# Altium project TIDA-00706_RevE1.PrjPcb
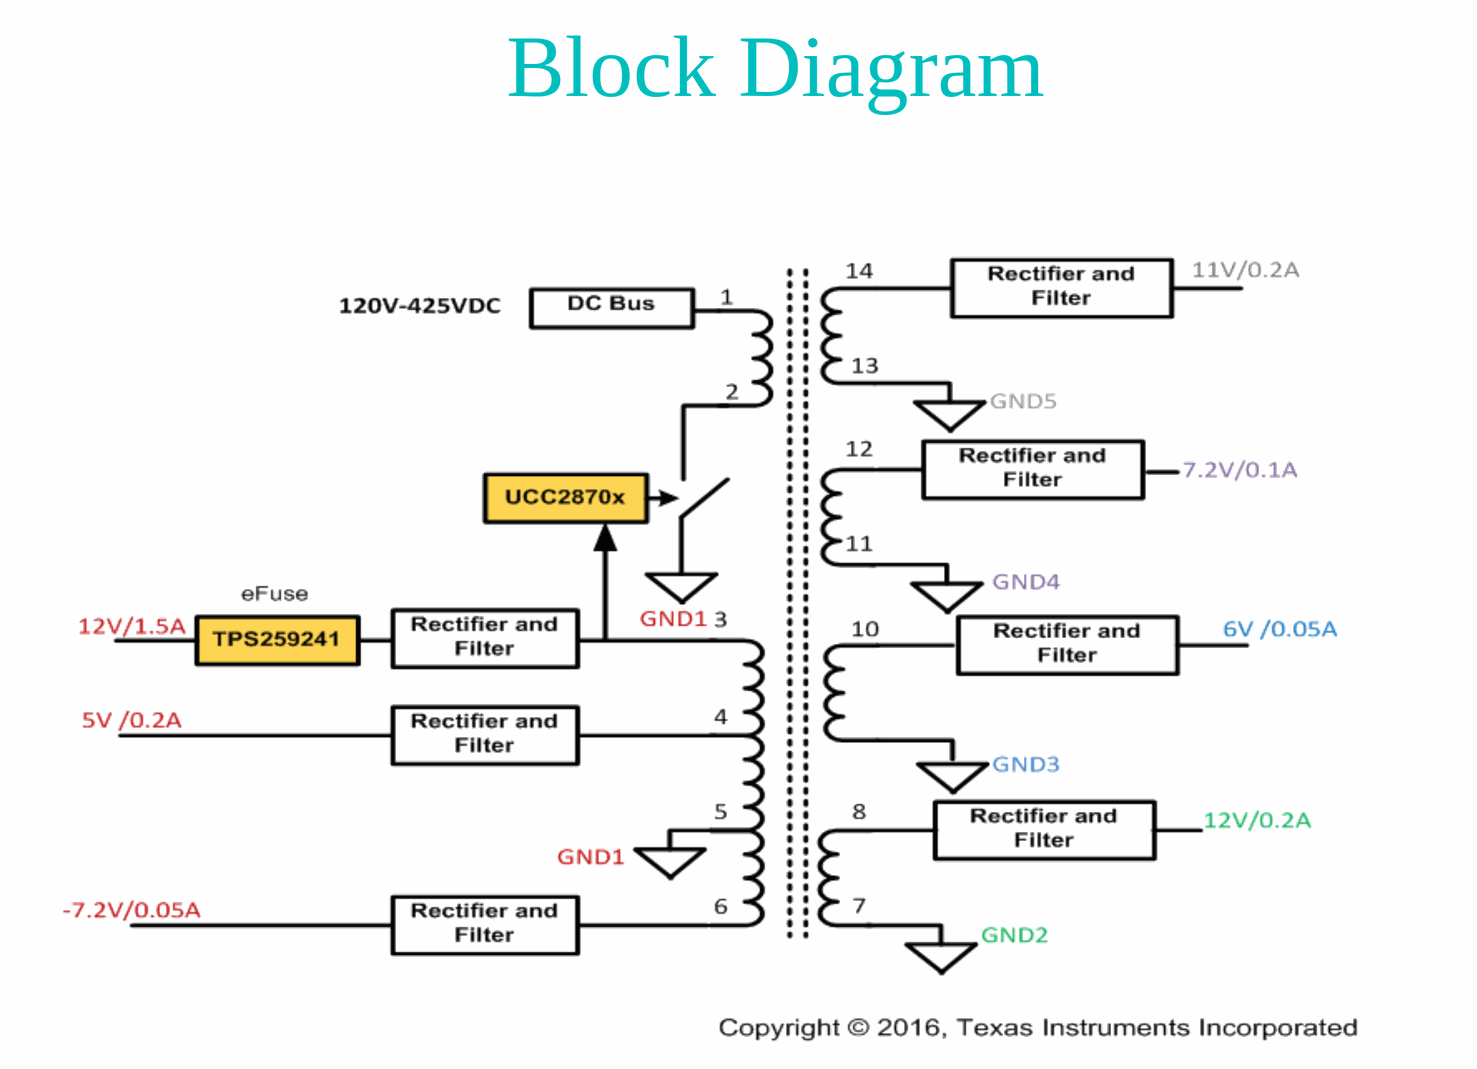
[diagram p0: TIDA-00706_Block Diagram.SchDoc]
CopyrightYear: 2016; EVM_Orderable: N/A; PCB_Layout: Manjunatha T N; PCB_Rev: E1; PRJ_Customer: Public Release; PRJ_Engineer: Neha Nain; PRJ_Number: TIDA-00706; PRJ_Title: 25W High Eff. Multipule output Auxilary Supply for Server PSU; SCH_Rev: E1; TechSupport: http://www.ti.com/support; TID: TIDA-00706
3 sheets, 66 parts. Net scope: flat (ports and power ports of the same name join across sheets).
Board file: TIDA-00706_RevE1.PcbDoc
Sheets:
  TIDA-00706_Block Diagram.SchDoc
  TIDA-00706_Schematics.SchDoc
  TIDA-00706_Hardware.SchDoc

## Sheet TIDA-00706_Block Diagram.SchDoc
size 431 x 304 mm; Date: Not shown in title block; ApprovedBy: Not shown in title block; CheckedBy: Not shown in title block; Author: Ramkumar S; CompanyName: Not shown in title block; DrawnBy: Naina Neha; Engineer: Naina Neha; Organization: Not shown in title block; Address1: Not shown in title block; Address2: Not shown in title block; Address3: Not shown in title block; Address4: Not shown in title block; DocumentNumber: 1; Revision: Use project parameter SCH_Rev; SheetNumber: 1; SheetTotal: 3; PageSetup: Record=PageOptions¦CenterHorizontal=True¦CenterVertical=True¦PrintScale=1.00¦XCorrection=1.00¦YCorrection=1.00¦PrintKind=0¦BorderSize=5000000¦LeftOffset=0¦BottomOffset=0¦Orientation=2¦PaperLength=1000¦PaperWidth=1000¦Scale=100¦PaperSource=15¦PrintQuality=600¦MediaType=1¦DitherType=10¦PaperKind=Letter¦PrintScaleMode=1

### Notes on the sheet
- Block Diagram

## Sheet TIDA-00706_Schematics.SchDoc
size 431 x 279 mm; Date: Not shown in title block; ApprovedBy: Not shown in title block; CheckedBy: Not shown in title block; Author: Not shown in title block; CompanyName: Not shown in title block; DrawnBy: Neha Nain; Engineer: Not shown in title block; Organization: Not shown in title block; Address1: Not shown in title block; Address2: Not shown in title block; Address3: Not shown in title block; Address4: Not shown in title block; DocumentNumber: 1; Revision: Use project parameter SCH_Rev; SheetNumber: 2; SheetTotal: 3; PageSetup: Record=PageOptions¦CenterHorizontal=True¦CenterVertical=True¦PrintScale=1.00¦XCorrection=1.00¦YCorrection=1.00¦PrintKind=0¦BorderSize=5000000¦LeftOffset=0¦BottomOffset=0¦Orientation=2¦PaperLength=1000¦PaperWidth=1000¦Scale=100¦PaperSource=15¦PrintQuality=600¦MediaType=1¦DitherType=10¦PaperKind=Letter¦PrintScaleMode=1
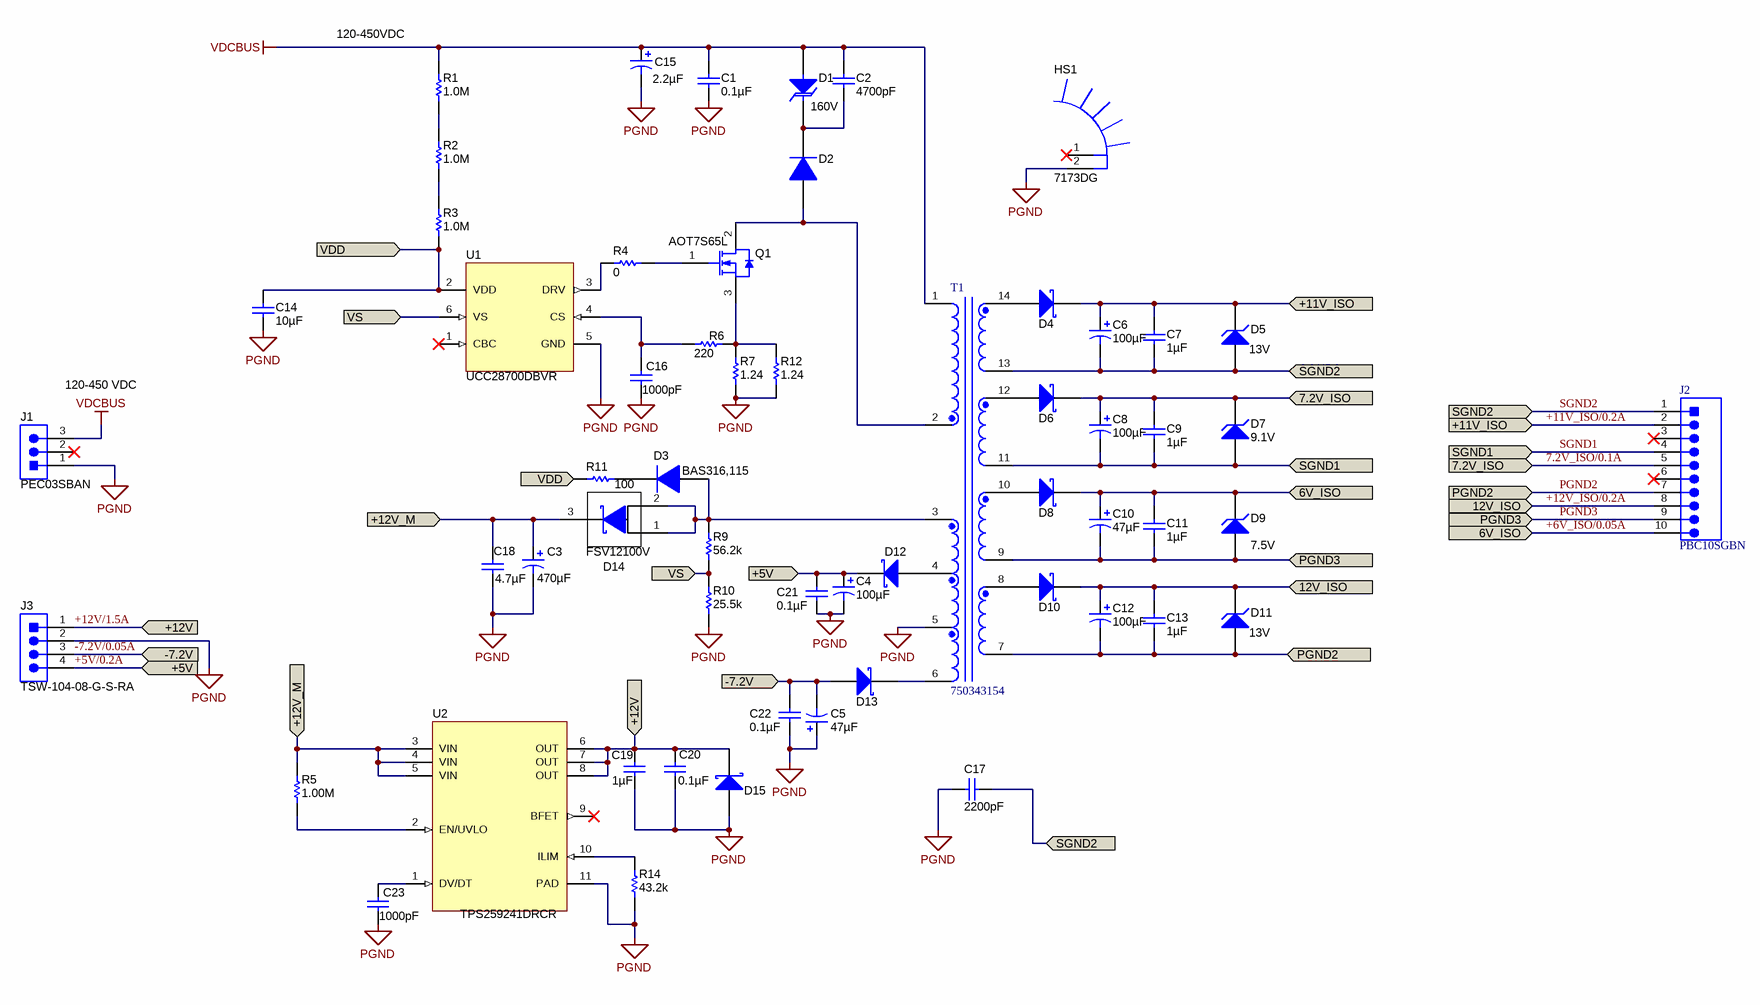
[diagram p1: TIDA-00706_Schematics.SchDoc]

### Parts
C1  ValueDisplayed: 0.1µF  [WCAP-FTXX_P10PL20_13x5x11]  (hidden comment: B32671P6104K)
C2  ValueDisplayed: 4700pF  [0603]  (hidden comment: C0603Y472K2RAC7867)
C3  ValueDisplayed: 470µF  [KZN_800x1150]  (hidden comment: EKZN250ELL471MH15D)
C4  ValueDisplayed: 100µF  [CAPPR2-5x11]  (hidden comment: 25YXJ100M5X11)
C5  ValueDisplayed: 47µF  [CAPPR2-5x11]  (hidden comment: UPW1E470MDD)
C6  ValueDisplayed: 100µF  [CAPPR2-5x11]  (hidden comment: 25YXJ100M5X11)
C7  ValueDisplayed: 1µF  [0603]  (hidden comment: C0603C105K3RACTU)
C8  ValueDisplayed: 100µF  [CAPPR2-5x11]  (hidden comment: 25YXJ100M5X11)
C9  ValueDisplayed: 1µF  [0603]  (hidden comment: C0603C105K3RACTU)
C10  ValueDisplayed: 47µF  [CAPPR2-5x11]  (hidden comment: UPW1E470MDD)
C11  ValueDisplayed: 1µF  [0603]  (hidden comment: C0603C105K3RACTU)
C12  ValueDisplayed: 100µF  [CAPPR2-5x11]  (hidden comment: 25YXJ100M5X11)
C13  ValueDisplayed: 1µF  [0603]  (hidden comment: C0603C105K3RACTU)
C14  ValueDisplayed: 10µF  [0603]  (hidden comment: GRM188R6YA106MA73D)
C15  ValueDisplayed: 2.2µF  [KZN_800x1150]  (hidden comment: UVY2W2R2MPD1TD)
C16  ValueDisplayed: 1000pF  [0603]  (hidden comment: GRM1885C1E102JA01D)
C17  ValueDisplayed: 2200pF  [E_900x700x900]  (hidden comment: CS80ZU2GA222MYNKA)
C18  ValueDisplayed: 4.7µF  [0603]  (hidden comment: C1608C0G1E472J080AA)
C19  ValueDisplayed: 1µF  [0603]  (hidden comment: C0603C105K3RACTU)
C20  ValueDisplayed: 0.1µF  [0603]  (hidden comment: 06033C104JAT2A)
C21  ValueDisplayed: 0.1µF  [0603]  (hidden comment: 06033C104JAT2A)
C22  ValueDisplayed: 0.1µF  [0603]  (hidden comment: 06033C104JAT2A)
C23  ValueDisplayed: 1000pF  [0603]  (hidden comment: GRM1885C1E102JA01D)
D1  value 160V  [SMB]  (hidden comment: SMBJ160A)
D2  US1M-13-F  [SMA]  (value not drawn)
D3  BAS316,115  [sod-323]
D4  PMEG10020AELRX  [SOD-123FL]  (value not drawn)
D5  value 13V  [SOD-123]  (hidden comment: MMSZ4700T1G)
D6  PMEG10020AELRX  [SOD-123FL]  (value not drawn)
D7  value 9.1V  [SOD-123]  (hidden comment: BZT52C9V1-7-F)
D8  PMEG10020AELRX  [SOD-123FL]  (value not drawn)
D9  value 7.5V  [SOD-123]  (hidden comment: MMSZ4693T1G)
D10  PMEG10020AELRX  [SOD-123FL]  (value not drawn)
D11  value 13V  [SOD-123]  (hidden comment: MMSZ5244BT1G)
D12  PMEG10020AELRX  [SOD-123FL]  (value not drawn)
D13  PMEG10020AELRX  [SOD-123FL]  (value not drawn)
D14  FSV12100V  [TO-277A]
D15  B0540WS-7  [sod-323]  (value not drawn)
HS1  7173DG  [HSINK_7173DG]
J1  PEC03SBAN  [Sullins_PEC03SBAN]
J2  PBC10SGBN  [SULLINS_PBC10SGBN]
J3  TSW-104-08-G-S-RA  [TSW-104-08-G-S-RA]
Q1  AOT7S65L  [TO-220_FullPAK_Offset]
R1  ValueDisplayed: 1.0M  [1206]  (hidden comment: CRCW12061M00JNEA)
R2  ValueDisplayed: 1.0M  [1206]  (hidden comment: CRCW12061M00JNEA)
R3  ValueDisplayed: 1.0M  [1206]  (hidden comment: CRCW12061M00JNEA)
R4  ValueDisplayed: 0  [0603]  (hidden comment: CRCW06030000Z0EA)
R5  ValueDisplayed: 1.00M  [0603]  (hidden comment: CRCW06031M00FKEA)
R6  ValueDisplayed: 220  [0603]  (hidden comment: RC0603FR-07220RL)
R7  ValueDisplayed: 1.24  [1206]  (hidden comment: CRCW12061R24FKEA)
R9  ValueDisplayed: 56.2k  [0603]  (hidden comment: RC0603FR-0756K2L)
R10  ValueDisplayed: 25.5k  [0603]  (hidden comment: RC0603FR-0725K5L)
R11  ValueDisplayed: 100  [0603]  (hidden comment: CRCW0603100RFKEA)
R12  ValueDisplayed: 1.24  [1206]  (hidden comment: CRCW12061R24FKEA)
R14  ValueDisplayed: 43.2k  [0603]  (hidden comment: CRCW060343K2FKEA)
T1  750343154  [XFMR_750343154_CUS]
U1  UCC28700DBVR  [DBV0006A_N]
U2  TPS259241DRCR  [DRC0010J]

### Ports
6V_ISO (in), 7.2V_ISO (in), 12V_ISO (in), +5V (in), +11V_ISO (in), +12V (in), +12V_M (in), -7.2V (in), PGND2 (in), PGND3 (in), SGND1 (in), SGND2 (in), VDD (in), VS (in)

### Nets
PGND: C1.2 C3.2(-) C4.2(-) C5.1(+) C14.2 C15.2(-) C16.2 C17.1 C18.2 C19.2 C20.2 C21.2 C22.2 C23.2 D15.2(A) HS1.2 J1.1 J3.2 R7.1 R10.1 R12.1 R14.1 T1.5 U1.5(GND) U2.11(PAD)
VDCBUS: C1.1 C2.1 C15.1(+) D1.2(A) J1.3 R1.2 T1.1
7.2V_ISO/0.1A: C8.1(+) C9.1 D6.1(K) D7.1(K) J2.5 ; port 7.2V_ISO
+5V/0.2A: C4.1(+) C21.1 D12.1(K) J3.4 ; port +5V
+6V_ISO/0.05A: C10.1(+) C11.1 D8.1(K) D9.1(K) J2.10 ; port 6V_ISO
+11V_ISO/0.2A: C6.1(+) C7.1 D4.1(K) D5.1(K) J2.2 ; port +11V_ISO
+12V/1.5A: C19.1 C20.1 D15.1(K) J3.1 U2.6(OUT) U2.7(OUT) U2.8(OUT) ; port +12V
+12V_ISO/0.2A: C12.1(+) C13.1 D10.1(K) D11.1(K) J2.8 ; port 12V_ISO
+12V_M: C3.1(+) C18.1 D14.3(K) R5.2 U2.3(VIN) U2.4(VIN) U2.5(VIN) ; port +12V_M
-7.2V/0.05A: C5.2(-) C22.1 D13.2(A) J3.3 ; port -7.2V
PGND2: C12.2(-) C13.2 D11.2(A) J2.7 T1.7 ; port PGND2
PGND3: C10.2(-) C11.2 D9.2(A) J2.9 T1.9 ; port PGND3
SGND1: C8.2(-) C9.2 D7.2(A) J2.4 T1.11 ; port SGND1
SGND2: C6.2(-) C7.2 C17.2 D5.2(A) J2.1 T1.13 ; port SGND2
VDD: C14.1 R3.1 R11.1 U1.2(VDD) ; port VDD
VS: R9.1 R10.2 U1.6(VS) ; port VS
NetC2_2: C2.2 D1.1(K) D2.1(K)
NetC16_1: C16.1 R6.1 U1.4(CS)
NetC23_1: C23.1 U2.1(DV/DT)
NetD2_2: D2.2(A) Q1.2(D) T1.2
NetD3_1: D3.1(K) R11.2
NetD3_2: D3.2(A) D14.1(A) D14.2(A) R9.2 T1.3
NetD4_2: D4.2(A) T1.14
NetD6_2: D6.2(A) T1.12
NetD8_2: D8.2(A) T1.10
NetD10_2: D10.2(A) T1.8
NetD12_2: D12.2(A) T1.4
NetD13_1: D13.1(K) T1.6
NetQ1_1: Q1.1(G) R4.1
NetQ1_3: Q1.3(S) R6.2 R7.2 R12.2
NetR1_1: R1.1 R2.2
NetR2_1: R2.1 R3.2
NetR4_2: R4.2 U1.3(DRV)
NetR5_1: R5.1 U2.2(EN/UVLO)
NetR14_2: R14.2 U2.10(ILIM)

Not connected (* = marked no-connect by the designer): HS1 1*; J1 2*; J2 3* 6*; U1 1(CBC)*; U2 9(BFET)*

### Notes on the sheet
- (near R1) 120-450VDC
- (near J1) 120-450 VDC

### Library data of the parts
C1 = 890334023006: CAP, Film, 0.1 µF, 630 V, +/- 10%, TH; Manufacturer: TDK; Polarized: N; CompType: Capacitor; Value: 0.1uF; U/M: EA; Cap_F: 0.00000001; Tolerance_%: 10; Value1: Unknown; VDC_V: 630; Value2: 630V; TaMin_C: -40; TaMax_C: 105; Cap_Case: 13x5x11mm; AEC Category: Q200
C2 = 06031C472JAT2A: CAP CER 4700PF 200V X7R 0603; Manufacturer: Kemet; Polarized: N; CompType: Capacitor; U/M: EA; Cap_F: 0.0000000047; Tolerance_%: 5; Value1: 0.136 ohm; VDC_V: 200; TaMin_C: -55; TaMax_C: 125; AEC Category: Q200
C3 = EKZN250ELL271MHB5D: CAP, AL, 470 µF, 25 V, +/- 20%, 0.075 ohm, TH; Manufacturer: United Chemi-Con; Polarized: Y; CompType: Capacitor; Value: 470uF; U/M: EA; Cap_F: 0.00047; Tolerance_%: 20; VDC_V: 25; Value2: 25V; ESR_ohm: 0.075; IRMS_A: 1.6; TaMin_C: -40; TaMax_C: 105; Cap_Case: 8x15mm; AEC Category: Q200
C4 C6 C8 C12 = UVR1V100MDD1TA: CAP, AL, 100 µF, 25 V, +/- 20%, TH; Manufacturer: Rubycon; Polarized: Y; CompType: Capacitor; Value: 100uF; U/M: EA; Cap_F: 0.00001; Tolerance_%: 20; Value1: Unknown; VDC_V: 25; Value2: 25V; TaMin_C: -40; TaMax_C: 85; Cap_Case: 5x11; AEC Category: Q200; AEC Qualified: N
C5 C10 = UVR1V100MDD1TA: CAP, AL, 47 µF, 25 V, +/- 20%, TH; Manufacturer: Nichicon; Polarized: Y; CompType: Capacitor; Value: 47uF; U/M: EA; Cap_F: 0.000047; Tolerance_%: 20; Value1: Unknown; VDC_V: 25; Value2: 25V; TaMin_C: -40; TaMax_C: 85; Cap_Case: 5x11; AEC Category: Q200; AEC Qualified: N
C7 C9 C11 C13 = C0603C105K8PACTU: CAP CER 1UF 25V X7R 0603; Manufacturer: Kemet; Polarized: N; CompType: Capacitor; U/M: EA; Cap_F: 0.000001; Tolerance_%: 10; Value1: Unknown; Value2: 10V; TempCo: X5R; TaMin_C: -55; TaMax_C: 85; AEC Category: Q200
C14 = GRM188R6YA106MA73: CAP, CERM, 10 µF, 35 V, +/- 20%, X5R, 0603; Manufacturer: Nichicon; Polarized: N; CompType: Capacitor; Value: 10uF; U/M: EA; Cap_F: 0.00001; Tolerance_%: 20; Value1: Unknown; VDC_V: 35; Value2: 35V; TaMin_C: -55; TaMax_C: 85; AEC Category: Q200
C15 = EKZN250ELL271MHB5D: CAP ALUM 2.2UF 20% 450V RADIAL; Manufacturer: Nichicon; Polarized: Y; CompType: Capacitor; U/M: EA; Value2: 25V; IRMS_A: 1.6; TaMin_C: -40; TaMax_C: 105; Cap_Case: 8x15mm; AEC Category: Q200
C16 C23 = GRM1885C1E102JA01D: CAP, CERM, 1000 pF, 25 V, +/- 5%, C0G/NP0, 0603; Manufacturer: MuRata; Polarized: N; CompType: Capacitor; Value: 1000pF; U/M: EA; Cap_F: 0.000000001; Tolerance_%: 5; Value1: Unknown; VDC_V: 25; Value2: 25V; TaMin_C: -55; TaMax_C: 125; AEC Category: Q200
C17 = DE6E3KJ222MN3A: CAP CER 2200PF 300VAC 20% RADIAL; Manufacturer: TDK Corporation; Polarized: N; CompType: Capacitor; Value: 2.2nF; U/M: EA; Cap_F: 0.0000000022; Tolerance_%: 20; Value1: Unknown; VDC_V: 300; Value2: 300V; TempCo: E; TaMin_C: -40; TaMax_C: 125
C18 = 0603ZD475KAT2A: CAP, CERM, 4.7 µF, 25 V, +/- 10%, 0603; Manufacturer: TDK Corporation; Polarized: N; CompType: Capacitor; Value: 4.7uF; U/M: EA; Cap_F: 0.0000047; Tolerance_%: 10; Value1: Unknown; Value2: 10V; TempCo: X5R; TaMin_C: -55; TaMax_C: 85; AEC Category: Q200
C19 = C0603C105K3RACTU: CAP, CERM, 1 µF, 25 V, +/- 10%, X7R, 0603; Manufacturer: Kemet; Polarized: N; CompType: Capacitor; Value: 1uF; U/M: EA; Cap_F: 0.000001; Tolerance_%: 10; Value1: Unknown; VDC_V: 25; Value2: 25V; TaMin_C: -55; TaMax_C: 125; AEC Category: Q200
C20-C22 = 06033C104JAT2A: CAP, CERM, 0.1 µF, 25 V, +/- 5%, X7R, 0603; Manufacturer: AVX; Polarized: N; CompType: Capacitor; Value: 0.1uF; U/M: EA; Cap_F: 0.0000001; Tolerance_%: 5; ESR_ohm: 0.05; Value1: 0.05 ohm; VDC_V: 25; Value2: 25V; TaMin_C: -55; TaMax_C: 125; AEC Category: Q200
D1 = SMBJ160A-13-F: TVS DIODE 160VWM 259VC SMB; Manufacturer: Fairchild Semiconductor; U/M: EA; Power_W: 5; Vr_V: 160; Value1: 5W; AEC Category: Q101
D2 = US1M-13-F: Diode, Ultrafast, 1000 V, 1 A, SMA; Manufacturer: Diodes Inc.; U/M: EA; Vf_V: 1.7; Value: 1000V; Value1: 1A; Value2: 1.7V; Io_A: 1; Vr_V: 1000; TJmax_C: 150; RJC_CperW: 30; AEC Category: Q101
D3 = BAS316,115: Diode, Ultrafast, 100V, 0.25A, SOD-323; Manufacturer: NXP Semiconductor; U/M: EA; Vf_V: 1.4; Value2: 1.4V; Io_A: 0.25; Vr_V: 100; TJmax_C: 150
D4 D6 D8 D10 = MBR1H100SFT3G: DIODE SCHOTTKY 100V 2A SOD2123; Manufacturer: NXP Semiconductors; U/M: EA; Vf_V: 0.85; Value: 150V; Value1: 1A; Value2: 0.85V; Io_A: 1; Vr_V: 200; AEC Category: Q101
D5 = MMSZ4700T1G: Diode, Zener, 13 V, 500 mW, SOD-123; Manufacturer: ON Semiconductor; SymbolCreator: a0412235; U/M: EA; Power_W: 0.5; Vz_V: 13; Value1: 0.5W; RJA_CperW: 340; AEC Category: Q101
D7 = BZT52B9V1-HE3-08: DIODE ZENER 9.1V 500MW SOD123; Manufacturer: Diodes Incorporated; SymbolCreator: a0412235; U/M: EA; Power_W: 0.5; Vz_V: 9.1; Value1: 0.5W; RJA_CperW: 300; AEC Category: Q101; AEC Qualified: Y
D9 = MMSZ4693T1G: Diode, Zener, 7.5 V, 500 mW, SOD-123; Manufacturer: ON Semiconductor; SymbolCreator: a0412235; U/M: EA; Power_W: 0.5; Vz_V: 7.5; Value1: 0.5W; RJA_CperW: 340; AEC Category: Q101
D11 = MMSZ4700T1G: Diode, Zener, 14 V, 500 mW, SOD-123; Manufacturer: ON Semiconductor; SymbolCreator: a0412235; U/M: EA; Power_W: 0.5; Vz_V: 13; Value1: 0.5W; RJA_CperW: 340; AEC Category: Q101
D12 D13 = MBR1H100SFT3G: DIODE SCHOTTKY 100V 2A SOD2123; Manufacturer: ON Semiconductor; U/M: EA; Vf_V: 0.94; Value: 200V; Value2: 0.94V; Io_A: 1; Vr_V: 200; TJmax_C: 175; RJC_CperW: 85; AEC Category: Q101
D14 = SS5P10-M3/86A: DIODE SCHOTTKY 100V 12A TO277-3; Manufacturer: Fairchild Semiconductor; U/M: EA; Vf_V: 0.88; Value2: 0.88V; Io_A: 12; Vr_V: 100
D15 = B0540WS-7: Diode, Schottky, 40 V, 0.5 A, SOD-323; Manufacturer: Diodes Inc.; U/M: EA; Vf_V: 0.55; Value: 40V; Value1: 0.5A; Value2: 0.55V; Io_A: 0.5; Vr_V: 40; TJmax_C: 125; AEC Category: Q101
HS1 = 7173DG: Heat Sink, TO-220 Vertical; Manufacturer: Aavid; SymbolCreator: a0799628
J1 = PEC03SBAN: Header, 100mil, 3x1, Tin, R/A, TH; Manufacturer: Sullins Connector Solutions; SymbolCreator: a0799628; U/M: EA
J2 = PBC10SGBN: CONNECTOR, HEADER, 2.54MM PITCH, 10 POS, RIGHT ANGLE, TH, ROHS; Manufacturer: SULLINS; SymbolCreator: x0199378
J3 = TSW-104-08-G-S-RA: Header, 100mil, 4x1, Gold, R/A, TH; Manufacturer: Samtec; SymbolCreator: a0412235; U/M: EA
Q1 = IPA60R385CP: MOSFET, N-CH, 650 V, 7 A, TO-220; Manufacturer: Alpha & Omega Semiconductor Inc.; Alternate Manufacturer: None; U/M: EA; ChType: N; Value: 650V; VdsMax_V: 650; Value1: ? ohm; Value2: 9.2 nC; QgTyp_nC: 9.2; Vgs_V: 4; IdsMax_A: 7; AEC Category: Q101
R1-R3 = CRCW12061M00JNEA: RES, 1.0 M, 5%, 0.25 W, 1206; Manufacturer: Vishay-Dale; CompType: Resistor; Value: 1.0Meg; Res_ohm: 1000000; Value_Code: 1M00; Tolerance_%: 5; Power_W: 0.25; Value2: 0.25W; VDC_V: 200; TempCo: 200 ppm/C; EIA_Code: E24; U/M: EA; AEC Category: Q200
R4 = CRCW06030000Z0EA: RES, 0, 5%, 0.1 W, 0603; Manufacturer: Vishay-Dale; CompType: Resistor; Value: 0; Value_Code: 0000; Tolerance_%: 5; Power_W: 0.1; Value2: 0.1W; VDC_V: 75; TempCo: 200 ppm/C; EIA_Code: E24; U/M: EA; AEC Category: Q200
R5 = CRCW06031M00FKEA: RES, 1.00 M, 1%, 0.1 W, 0603; Manufacturer: Vishay-Dale; CompType: Resistor; Value: 1.00Meg; Res_ohm: 1000000; Value_Code: 1M00; Tolerance_%: 1; Power_W: 0.1; Value2: 0.1W; VDC_V: 75; TempCo: 100 ppm/C; EIA_Code: E96; U/M: EA; AEC Category: Q200
R6 = RC0603FR-07220RL: RES, 220, 1%, 0.1 W, 0603; Manufacturer: Yageo America; CompType: Resistor; Value: 220; Value_Code: 220R; Tolerance_%: 1; Power_W: 0.1; Value2: 0.1W; VDC_V: 150; TempCo: 200 ppm/C; U/M: EA; AEC Category: Q200
R7 R12 = CRCW12061R24FKEA: RES, 1.24, 1%, 0.25 W, 1206; Manufacturer: Vishay-Dale; CompType: Resistor; Value: 1.24; Value_Code: 1R24; Tolerance_%: 1; Power_W: 0.25; Value2: 0.25W; VDC_V: 200; TempCo: 100 ppm/C; EIA_Code: E96; U/M: EA; AEC Category: Q200
R9 = CRCW060310K0FKEA: RES SMD 56.2K OHM 1% 1/10W 0603; Manufacturer: Yageo; CompType: Resistor; Res_ohm: 10000; Tolerance_%: 1; Power_W: 0.1; Value2: 0.1W; VDC_V: 75; TempCo: 100 ppm/C; EIA_Code: E96; U/M: EA; AEC Category: Q200
R10 = CRCW06034K64FKEA: RES SMD 25.5K OHM 1% 1/10W 0603; Manufacturer: Yageo; CompType: Resistor; Res_ohm: 4640; Tolerance_%: 1; Power_W: 0.1; Value2: 0.1W; VDC_V: 75; TempCo: 100 ppm/C; EIA_Code: E96; U/M: EA; AEC Category: Q200
R11 = CRCW0603100RFKEA: RES, 100, 1%, 0.1 W, 0603; Manufacturer: Vishay-Dale; CompType: Resistor; Value: 100; Value_Code: 100R; Tolerance_%: 1; Power_W: 0.1; Value2: 0.1W; VDC_V: 75; TempCo: 100 ppm/C; EIA_Code: E96; U/M: EA; AEC Category: Q200
R14 = CRCW060343K2FKEA: RES, 43.2 k, 1%, 0.1 W, 0603; Manufacturer: Vishay-Dale; CompType: Resistor; Value: 43.2k; Res_ohm: 43200; Value_Code: 43k2; Tolerance_%: 1; Power_W: 0.1; Value2: 0.1W; VDC_V: 75; TempCo: 100 ppm/C; EIA_Code: E96; U/M: EA; AEC Category: Q200
U1 = UCC28700DBVR: Constant-Voltage, Constant-Current Controller With Primary-Side Regulation, DBV0006A; Alternate PartNumber: UCC28700DBVT; Manufacturer: Texas Instruments; SymbolCreator: a0799628; CompType: IC; U/M: EA
U2 = TPS259241DRCR: 12-V eFuse with Over Voltage Protection and Blocking FET Control, DRC0010J; Alternate PartNumber: TPS259241DRCT; Manufacturer: Texas Instruments; SymbolCreator: a0799628; CompType: IC; U/M: EA

## Sheet TIDA-00706_Hardware.SchDoc
size 431 x 279 mm; Date: Not shown in title block; ApprovedBy: Not shown in title block; CheckedBy: Not shown in title block; Author: Not shown in title block; CompanyName: Not shown in title block; DrawnBy: Neha Nain; Engineer: Not shown in title block; Organization: Not shown in title block; Address1: Not shown in title block; Address2: Not shown in title block; Address3: Not shown in title block; Address4: Not shown in title block; DocumentNumber: 1; Revision: Use project parameter SCH_Rev; SheetNumber: 3; SheetTotal: 3; PageSetup: Record=PageOptions¦CenterHorizontal=True¦CenterVertical=True¦PrintScale=1.00¦XCorrection=1.00¦YCorrection=1.00¦PrintKind=0¦BorderSize=5000000¦LeftOffset=0¦BottomOffset=0¦Orientation=2¦PaperLength=1000¦PaperWidth=1000¦Scale=100¦PaperSource=15¦PrintQuality=600¦MediaType=1¦DitherType=10¦PaperKind=Letter¦PrintScaleMode=1
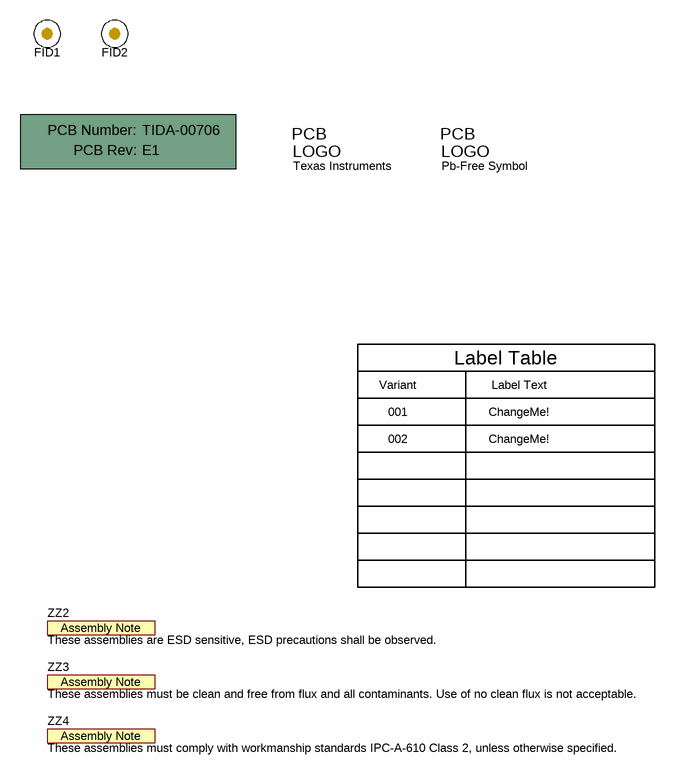
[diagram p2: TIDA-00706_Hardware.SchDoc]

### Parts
!PCB1  Printed Circuit Board  (value not drawn)  (mechanical)
FID1  Fiducial  [Fiducial10-20]  (value not drawn)
FID2  Fiducial  [Fiducial10-20]  (value not drawn)
Logo1  Texas Instruments  [TI_Symbol_Overlay_Small]  (no BOM)
Logo2  Pb-Free Symbol  [Pb-Free_Overlay_Small]  (no BOM)
ZZ2  These assemblies are ESD sensitive, ESD precautions shall be observed.  [AssemblyNote]  (no BOM)
ZZ3  These assemblies must be clean and free from flux and all contaminants. Use of no clean flux is not acceptable.  [AssemblyNote]  (no BOM)
ZZ4  These assemblies must comply with workmanship standards IPC-A-610 Class 2, unless otherwise specified.  [AssemblyNote]  (no BOM)

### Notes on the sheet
- Variant
- Label Table
- Label Text
- 001
- 002
- ChangeMe!

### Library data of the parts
!PCB1 = PCB: Manufacturer: Any; PartNumber: TIDA-00706; SymbolCreator: a0412235
FID1 FID2 = Fiducial: Fiducial mark.  There is nothing to buy or mount.; SymbolCreator: codlsc
Logo1 = TI_Logo: Texas Instrument Corporate Signature; SymbolCreator: codlsc
Logo2 = Pb-Free: SymbolCreator: a0412235
ZZ2-ZZ4 = AssemblyNote: SymbolCreator: codlsc

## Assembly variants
001: not fitted C15 FID1 FID2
